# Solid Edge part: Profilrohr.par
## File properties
Username: bmolnar
Dokumentum tartalom típus: 0
Author: bmolnar
Last saved by: bmolnar
Revision: 79
Sűrűség: 0,000 kg/m^3
Pontosság: 0,990
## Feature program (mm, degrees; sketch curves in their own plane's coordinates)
base feature "unnamed BaseFeature 1"
thread "unnamed Thread 1"
thread "Menet_2"  ThreadDepth = 7.5 mm
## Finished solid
Body 1: solid body, 165 faces, 370 edges, 228 vertices, 3 separate solids.
  Faces by surface: plane 100, cylinder 43, cone 18, torus 4
  Edges by curve: line 256, circle 106, curve on surface 7, intersection 1
Bounding box of the edges (mm; curved faces can reach further): 80.000 x 86.000 x 57.000, from (-40, -40, 0) to (40, 46, 57).
Cylindrical faces by radius (mm): R1.6 x2, R4 x2, R4.283 x4, R4.55 x7, R4.555 x1, R6.9 x2, R7 x14, R31.5 x1, R32.35 x2, R32.55 x2, R34.1 x2, R53 x4
Conical faces (half-angle, radius in mm at the cone's reference point): 30 deg R31.825 x2, 30 deg R32.6387 x2, 45 deg R4.25 x4, 45 deg R4.533 x2, 45 deg R6.65 x4, 45 deg R32.7 x2, 45 deg R32.8 x2
Toroidal faces (ring radius, tube radius in mm): R33.9 r0.2 x4
Planar faces by outward normal: +x 9, +y 11, +z 12, -x 9, -y 9, -z 10, oblique 40
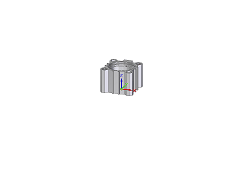
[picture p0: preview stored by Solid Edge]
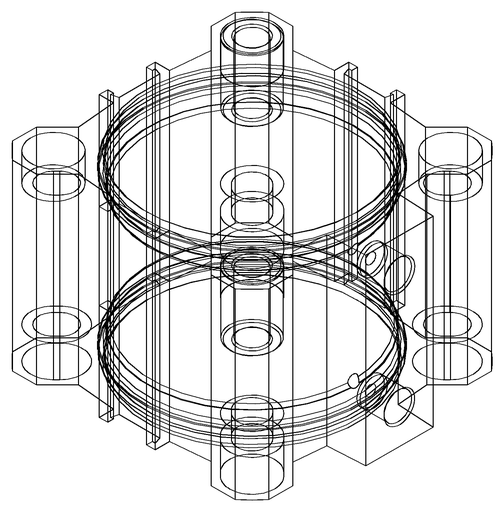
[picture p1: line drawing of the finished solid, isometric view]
